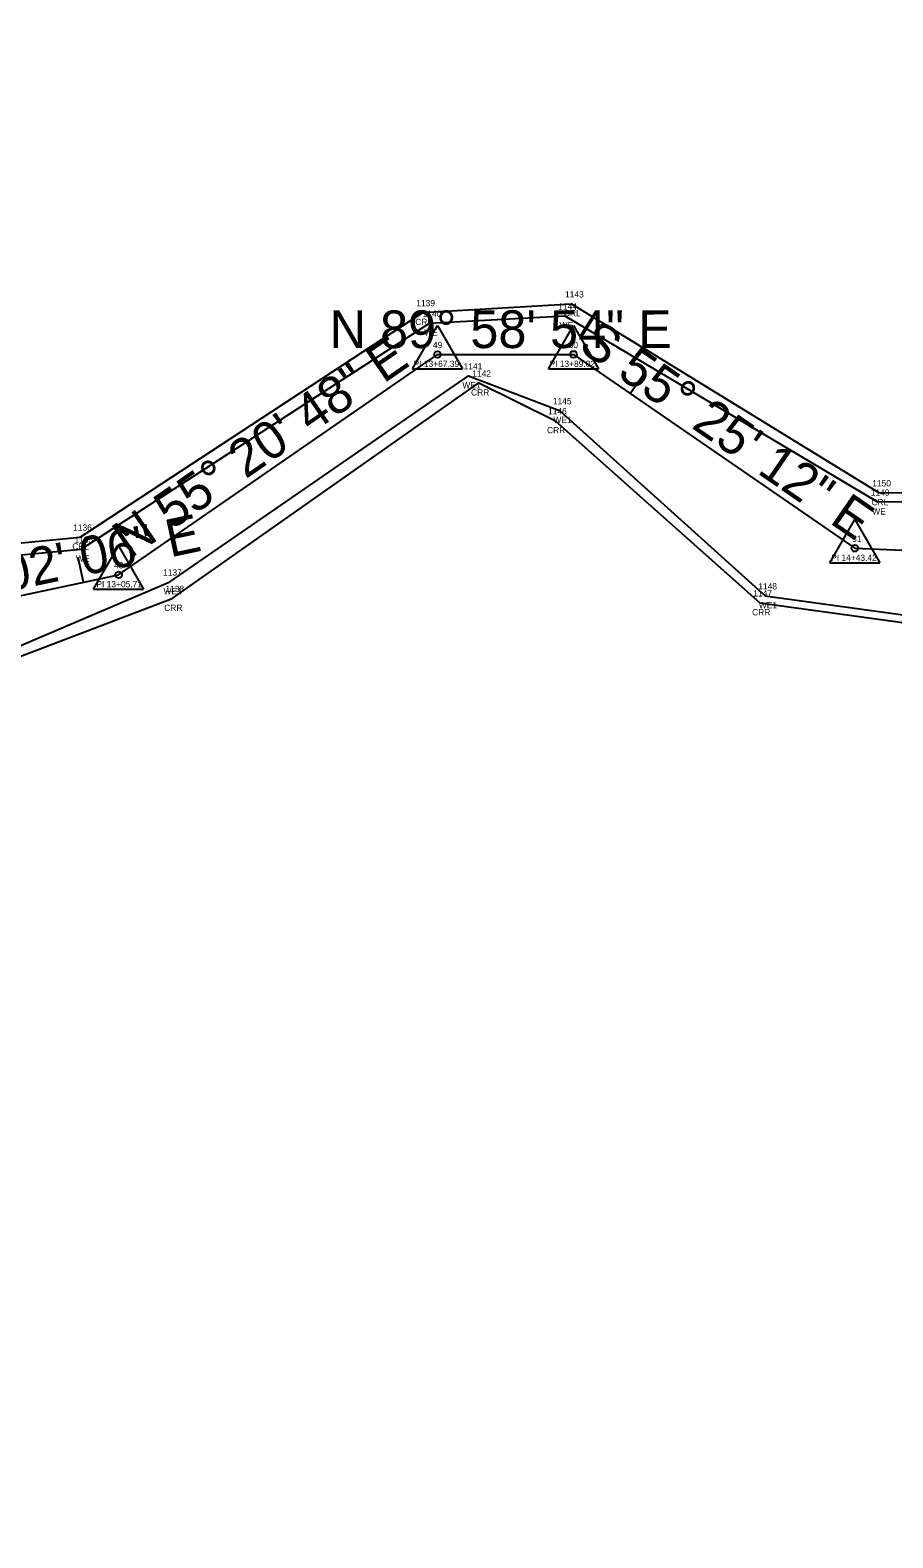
# Model space of a CAD drawing. Extents: x 2445178 to 2446205, y 790762 to 792372.
# Drawn here: x 2445920.2 to 2446057.5, y 791778.3 to 792018.2 of the extents above; entities that cross this region are included whole.
import ezdxf

# ---------------------------------------------------------------- set-up
doc = ezdxf.new("R2010")
doc.units = 0
for name, color, linetype in [('RD_EX_H2O', 7, 'Continuous'), ('RD_EX_H2O_txCode', 7, 'Continuous'), ('RD_HC_Cl', 7, 'Continuous'), ('RD_HC_Data', 7, 'Continuous'), ('RD_HC_Data_Tic', 7, 'Continuous'), ('RD_HC_txCode', 7, 'Continuous'), ('RD_SMD_Locator', 7, 'Continuous')]:
    doc.layers.add(name, color=color, linetype=linetype)

msp = doc.modelspace()

# ---------------------------------------------------------------- linework, layer by layer
at = {"layer": 'RD_EX_H2O'}
for points in [[(2445749.98, 791821.69), (2445784.5, 791816.33), (2445784.5, 791816.33), (2445826.97, 791831.85), (2445864.4, 791840.41), (2445865.35, 791848.28), (2445857.59, 791890.6), (2445862.25, 791903.98), (2445902.88, 791935.07), (2445928.13, 791937.54), (2445982.7, 791973.27), (2446006.36, 791974.66), (2446055.29, 791944.59), (2446112.86, 791944.82), (2446116.06, 791949.26), (2446125.53, 791975.87), (2446156.76, 791972.15), (2446187.24, 792018.21)], [(2445757.3, 791817.48), (2445784.85, 791815.29), (2445827.3, 791828.95), (2445865.88, 791838.48), (2445867.77, 791849.3), (2445858.86, 791890.39), (2445863.96, 791902.52), (2445903.58, 791933.29), (2445928.32, 791935.62), (2445983.75, 791971.59), (2446005.28, 791972.74), (2446055.03, 791943.12), (2446113.69, 791943.23), (2446117.06, 791949.31), (2446126.55, 791974.16), (2446158.67, 791970.49), (2446188.67, 792015.57)], [(2445748.32, 791780.49), (2445788.24, 791788.44), (2445846, 791811.01), (2445891.85, 791826.96), (2445872.2, 791885.31), (2445911.58, 791917.24), (2445942.41, 791930.41), (2445989.95, 791963.2), (2446004.43, 791957.67), (2446037.13, 791928.19), (2446062.94, 791924.63), (2446122.42, 791925.89), (2446133.98, 791956.62), (2446163.05, 791958.48), (2446202.11, 792005.16)], [(2445746.88, 791778.25), (2445790.91, 791782.86), (2445846.87, 791809.11), (2445896.01, 791824.25), (2445877, 791883.78), (2445912.26, 791916.16), (2445942.78, 791927.77), (2445991.6, 791962.06), (2446003.69, 791956.06), (2446036.32, 791927.07), (2446060.96, 791923.67), (2446122.97, 791923.97), (2446134.24, 791956.18), (2446163.21, 791958.01), (2446202.51, 792004.24)]]:
    msp.add_lwpolyline(points, dxfattribs=at)
at = {"layer": 'RD_HC_Cl'}
for p, q in [((2445934.28, 791931.53), (2445985.01, 791966.6)), ((2445985.01, 791966.6), (2446006.65, 791966.61)), ((2446006.65, 791966.61), (2446051.43, 791935.74)), ((2446051.43, 791935.74), (2446117.74, 791933.18)), ((2445909.8, 791926.34), (2445934.28, 791931.53))]:
    msp.add_line(p, q, dxfattribs=at)
at = {"layer": 'RD_HC_Data'}
for p, q in [((2445981.04, 791964.31), (2445985.01, 791971.19)), ((2445985.01, 791971.19), (2445988.98, 791964.31)), ((2446002.68, 791964.32), (2446006.65, 791971.2)), ((2446006.65, 791971.2), (2446010.62, 791964.32)), ((2445981.04, 791964.31), (2445988.98, 791964.31)), ((2446002.68, 791964.32), (2446010.62, 791964.32)), ((2446047.46, 791933.44), (2446051.43, 791940.32)), ((2446051.43, 791940.32), (2446055.4, 791933.44)), ((2445930.3, 791929.24), (2445934.28, 791936.12)), ((2445934.28, 791936.12), (2445938.25, 791929.24)), ((2446047.46, 791933.44), (2446055.4, 791933.44)), ((2445930.3, 791929.24), (2445938.25, 791929.24))]:
    msp.add_line(p, q, dxfattribs=at)
for centre in [(2445985.01, 791966.6), (2446006.65, 791966.61), (2446051.43, 791935.74), (2445934.28, 791931.53)]:
    msp.add_circle(centre, 0.529, dxfattribs=at)
at = {"layer": 'RD_HC_Data_Tic'}
for p, q in [((2446015.69, 791960.38), (2446017.96, 791963.67)), ((2445928.69, 791930.35), (2445927.86, 791934.26))]:
    msp.add_line(p, q, dxfattribs=at)
at = {"layer": 'RD_SMD_Locator'}
for centre in [(2446006.36, 791974.66), (2445982.7, 791973.27), (2445983.75, 791971.59), (2446005.28, 791972.74), (2445985.01, 791966.6), (2446006.65, 791966.61), (2445989.95, 791963.2), (2445991.6, 791962.06), (2446004.43, 791957.67), (2446003.69, 791956.06), (2446055.03, 791943.12), (2446055.29, 791944.59), (2445928.13, 791937.54), (2445928.32, 791935.62), (2446051.43, 791935.74), (2445934.28, 791931.53), (2445942.41, 791930.41), (2445942.78, 791927.77), (2446036.32, 791927.07), (2446037.13, 791928.19)]:
    msp.add_circle(centre, 0.001, dxfattribs=at)

# ---------------------------------------------------------------- texts
at = {"layer": 'RD_EX_H2O_txCode'}
for s, p in [('1143', (2446005.3, 791975.66)), ('1139', (2445981.64, 791974.27)), ('1144', (2446004.22, 791973.74)), ('CRL', (2445981.47, 791971.27)), ('1140', (2445982.64, 791972.59)), ('WE', (2446004.44, 791970.74)), ('CRL', (2446005.13, 791972.66)), ('WE', (2445982.91, 791969.59)), ('1141', (2445989.17, 791964.2)), ('WE1', (2445988.97, 791961.2)), ('1142', (2445990.54, 791963.06)), ('CRR', (2445990.35, 791960.06)), ('1145', (2446003.37, 791958.67)), ('1146', (2446002.6, 791957.06)), ('CRR', (2446002.44, 791954.06)), ('WE1', (2446003.45, 791955.67)), ('1150', (2446054.19, 791945.59)), ('1149', (2446053.96, 791944.12)), ('CRL', (2446054.06, 791942.59)), ('WE', (2446054.19, 791941.12)), ('1136', (2445927.04, 791938.54)), ('CRL', (2445926.9, 791935.54)), ('1135', (2445927.26, 791936.62)), ('WE', (2445927.48, 791933.62)), ('1137', (2445941.35, 791931.41)), ('WE1', (2445941.42, 791928.41)), ('1138', (2445941.72, 791928.77)), ('1147', (2446035.26, 791928.07)), ('1148', (2446036.06, 791929.19)), ('CRR', (2445941.53, 791925.77)), ('CRR', (2446035.07, 791925.07)), ('WE1', (2446036.14, 791926.19))]:
    msp.add_text(s, height=1, dxfattribs=at).set_placement(p)
at = {"layer": 'RD_HC_Data'}
for s, rotation, p in [('N 89%%d 58\' 54" E', 0.0183, (2445967.85, 791967.6)), ('N 55%%d 20\' 48" E', 34.6532, (2445936.06, 791933.98)), ('S 55%%d 25\' 12" E', 325.4199, (2446007.18, 791967.46)), ('N 78%%d 02\' 06" E', 11.965, (2445894.46, 791924.11))]:
    msp.add_text(s, height=6, rotation=rotation, dxfattribs=at).set_placement(p)
at = {"layer": 'RD_HC_txCode'}
for s, p in [('49', (2445984.28, 791967.6)), ('50', (2446005.88, 791967.61)), ('PI 13+67.39', (2445981.21, 791964.6)), ('PI 13+89.02', (2446002.83, 791964.61)), ('51', (2446050.98, 791936.74)), ('48', (2445933.54, 791932.53)), ('PI 14+43.42', (2446047.65, 791933.74)), ('PI 13+05.71', (2445930.74, 791929.53))]:
    msp.add_text(s, height=1, dxfattribs=at).set_placement(p)

doc.saveas('drawing.dxf')
